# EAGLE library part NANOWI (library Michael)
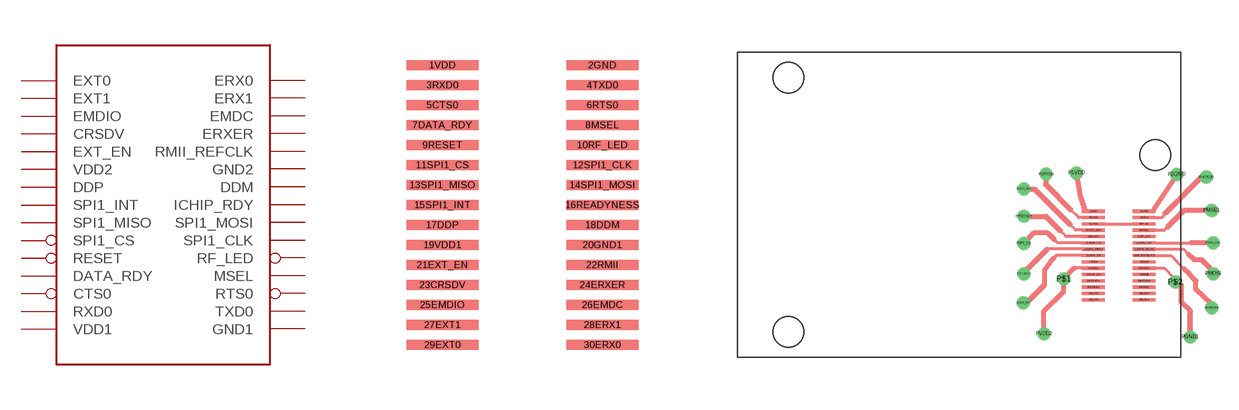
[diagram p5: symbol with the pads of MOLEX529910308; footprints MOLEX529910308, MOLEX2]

Designator prefix -

## NANOWI  [MOLEX529910308]
1VDD  VDD1  pwr
2GND  GND1  pwr
3RXD0  RXD0  in
4TXD0  TXD0  out
5CTS0  CTS0  in
6RTS0  RTS0  out
7DATA_RDY  DATA_RDY  out
8MSEL  MSEL  in
9RESET  RESET  in
10RF_LED  RF_LED  out
11SPI1_CS  SPI1_CS  in
12SPI1_CLK  SPI1_CLK  in
13SPI1_MISO  SPI1_MISO  out
14SPI1_MOSI  SPI1_MOSI  in
15SPI1_INT  SPI1_INT  out
16READYNESS  ICHIP_RDY  out
17DDP  DDP
18DDM  DDM
19VDD1  VDD2  pwr
20GND1  GND2  pwr
21EXT_EN  EXT_EN  out
22RMII  RMII_REFCLK  in
23CRSDV  CRSDV  in
24ERXER  ERXER  in
25EMDIO  EMDIO
26EMDC  EMDC  out
27EXT1  EXT1  out
28ERX1  ERX1  in
29EXT0  EXT0  out
30ERX0  ERX0  in

## NANOWIBREAKOUT  [MOLEX2]
5CTS0  CTS0  in
6RTS0  RTS0  out
10RF_LED  RF_LED  out
17DDP  DDP
18DDM  DDM
21EXT_EN  EXT_EN  out
22RMII  RMII_REFCLK  in
23CRSDV  CRSDV  in
24ERXER  ERXER  in
25EMDIO  EMDIO
26EMDC  EMDC  out
27EXT1  EXT1  out
28ERX1  ERX1  in
29EXT0  EXT0  out
30ERX0  ERX0  in
P1VDD  VDD1  pwr
P2GND  GND2  pwr
P3RXD0  RXD0  in
P4TXD0  TXD0  out
PDATA_RDY  DATA_RDY  out
PGND1  GND1  pwr
PICHIP_RDY  ICHIP_RDY  out
PMOSI  SPI1_MOSI  in
PMSEL  MSEL  in
PRESET  RESET  in
PSPI_CLK  SPI1_CLK  in
PSPI_CS  SPI1_CS  in
PSPI_INT  SPI1_INT  out
PSPI_MISO  SPI1_MISO  out
PVDD2  VDD2  pwr

## Footprint MOLEX529910308 (pad centres in mm)
smd 1.8 x 0.25: 1VDD -2,3.5; 2GND 2,3.5; 3RXD0 -2,3; 4TXD0 2,3; 5CTS0 -2,2.5; 6RTS0 2,2.5; 7DATA_RDY -2,2; 8MSEL 2,2; 9RESET -2,1.5; 10RF_LED 2,1.5; 11SPI1_CS -2,1; 12SPI1_CLK 2,1; 13SPI1_MISO -2,0.5; 14SPI1_MOSI 2,0.5; 15SPI1_INT -2,0; 16READYNESS 2,0; 17DDP -2,-0.5; 18DDM 2,-0.5; 19VDD1 -2,-1; 20GND1 2,-1; 21EXT_EN -2,-1.5; 22RMII 2,-1.5; 23CRSDV -2,-2; 24ERXER 2,-2; 25EMDIO -2,-2.5; 26EMDC 2,-2.5; 27EXT1 -2,-3; 28ERX1 2,-3; 29EXT0 -2,-3.5; 30ERX0 2,-3.5

## Footprint MOLEX2 (pad centres in mm)
smd 1.8 x 0.25: 1VDD 11.7,-0.25; 2GND 15.7,-0.25; 3RXD0 11.7,-0.75; 4TXD0 15.7,-0.75; 5CTS0 11.7,-1.25; 6RTS0 15.7,-1.25; 7DATA_RDY 11.7,-1.75; 8MSEL 15.7,-1.75; 9RESET 11.7,-2.25; 10RF_LED 15.7,-2.25; 11SPI1_CS 11.7,-2.75; 12SPI1_CLK 15.7,-2.75; 13SPI1_MISO 11.7,-3.25; 14SPI1_MOSI 15.7,-3.25; 15SPI1_INT 11.7,-3.75; 16READYNESS 15.7,-3.75; 17DDP 11.7,-4.25; 18DDM 15.7,-4.25; 19VDD1 11.7,-4.75; 20GND1 15.7,-4.75; 21EXT_EN 11.7,-5.25; 22RMII 15.7,-5.25; 23CRSDV 11.7,-5.75; 24ERXER 15.7,-5.75; 25EMDIO 11.7,-6.25; 26EMDC 15.7,-6.25; 27EXT1 11.7,-6.75; 28ERX1 15.7,-6.75; 29EXT0 11.7,-7.25; 30ERX0 15.7,-7.25
drill 0.5 pad 1.016 round: P1VDD 10.36,2.77; P2GND 18.27,2.64; P3RXD0 7.96,2.68; P4TXD0 20.61,2.45; P$1 9.35,-5.6; P$2 18.15,-5.85; PDATA_RDY 6.2,1.5; PGND1 19.35,-10.2; PICHIP_RDY 21.05,-7.9; PMOSI 21.15,-5.2; PMSEL 21.05,-0.2; PRESET 6.2,-0.65; PSPI_CLK 21.15,-2.75; PSPI_CS 6.2,-2.8; PSPI_INT 6.15,-7.5; PSPI_MISO 6.2,-5.2; PVDD2 7.8,-9.95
